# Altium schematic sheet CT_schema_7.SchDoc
size 287 x 160 mm
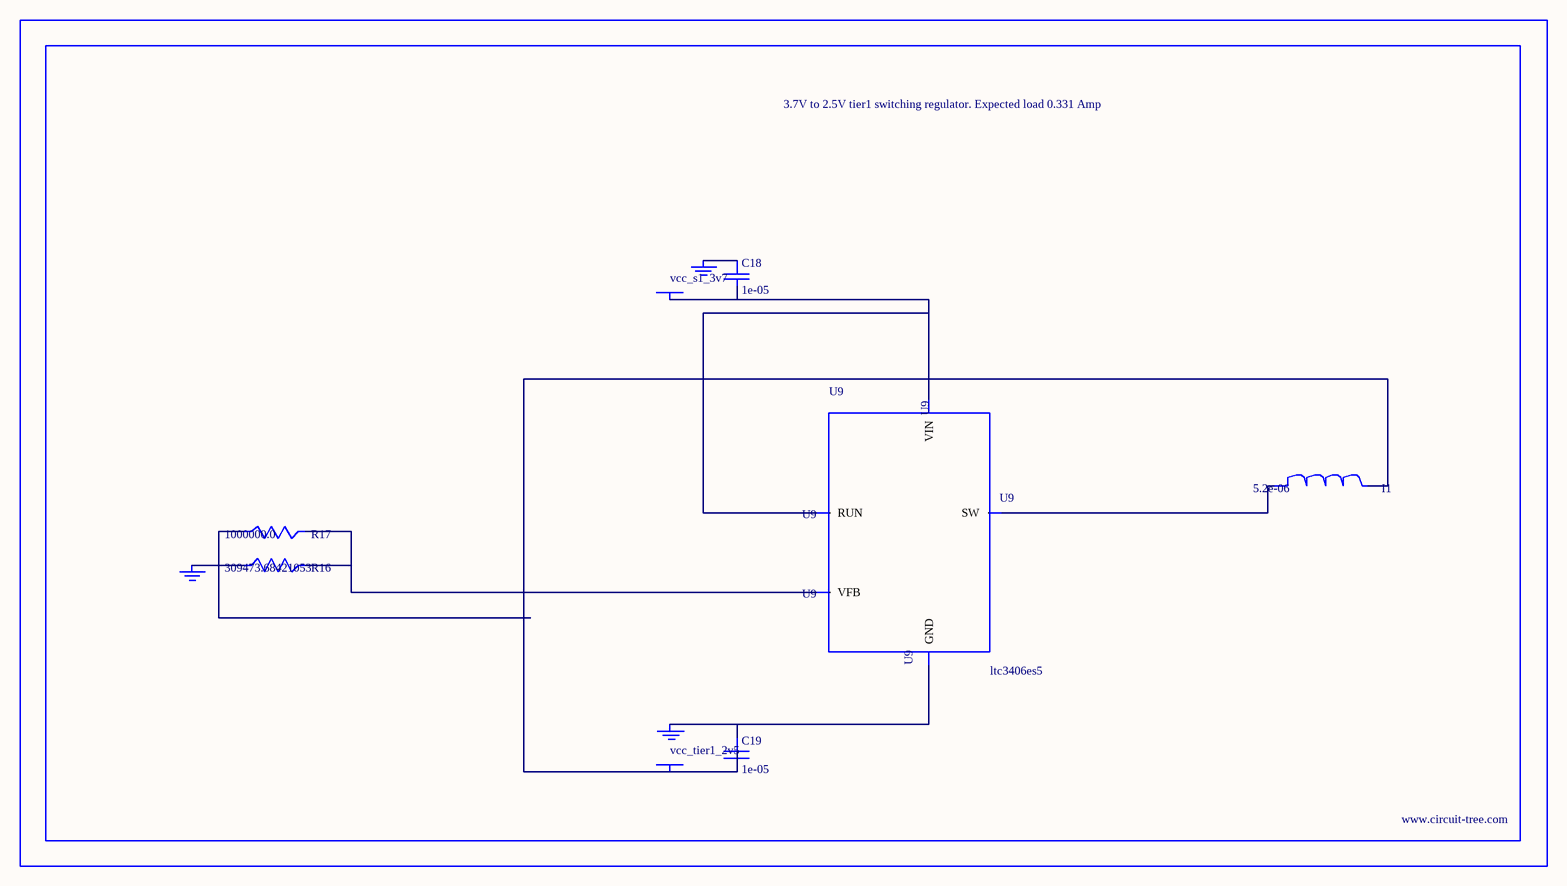
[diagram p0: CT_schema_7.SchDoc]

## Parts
BORDER6  (no value)
C18  1e-05  [C0805]
C19  1e-05  [C0805]
GND_INSTANCE_6_0  (no value)
GND_INSTANCE_6_1  (no value)
GND_INSTANCE_6_2  (no value)
I1  5.2e-06  [DR1040]
POWER_INSTANCE_6_0  vcc_tier1_2v5
POWER_INSTANCE_6_1  vcc_s1_3v7
R16  309473.68421053  [R0603]
R17  1000000.0  [R0603]
U9  ltc3406es5  [TSOT-23-5]

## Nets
NetC18_1: C18.1 GND_INSTANCE_6_1.0(GND)
NetC18_2: C18.2 POWER_INSTANCE_6_1.0(PWR) U9.1(RUN) U9.4(VIN)
NetC19_1: C19.1 GND_INSTANCE_6_0.0(GND) U9.2(GND)
NetC19_2: C19.2 I1.2 POWER_INSTANCE_6_0.0(PWR) R17.1
NetGND_INSTANCE_6_2_0: GND_INSTANCE_6_2.0(GND) R16.1
NetI1_1: I1.1 U9.3(SW)
NetR16_2: R16.2 R17.2 U9.5(VFB)

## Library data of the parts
BORDER6 = BORDER_PAGE6
C18 C19 = C0805C106K8RACTU
GND_INSTANCE_6_0-GND_INSTANCE_6_2 = GND
I1 = DR1040-5R2-R
POWER_INSTANCE_6_0 POWER_INSTANCE_6_1 = PWR
R16 = R16
R17 = RC0603JR-071ML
